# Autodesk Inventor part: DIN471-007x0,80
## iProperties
Created: 2006-01
Part Number: DIN471-007x0,80
Material: Federstahl
Catalog Web Link: http://www.seeger-orbis.de
Description: Sicherungsring
Vendor: Seeger-Orbis GmbH
Document SubType Name: Modeling
Control State: 0
Master: False
Checked Out: False
Shininess: 64.0
Angle Display Precision: 2
Document Length Units: 11269
Document Angle Units: 11279
Document Time Units: 11290
Document Mass Units: 11283
Document Length Units Precision: 3
Document Angle Units Precision: 2
Compacted: True
Density: 0.0
Volumn: 0.0
Area: 0.0
PropertySet Name: Model Information
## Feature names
1. Extrusion1
2. Extrusion2
